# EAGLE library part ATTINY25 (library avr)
MICROCONTROLLER 2 Kbytes FLASH 128 bytes EEPROM 128 bytes RAM 4-channel 10 bit ADC USI
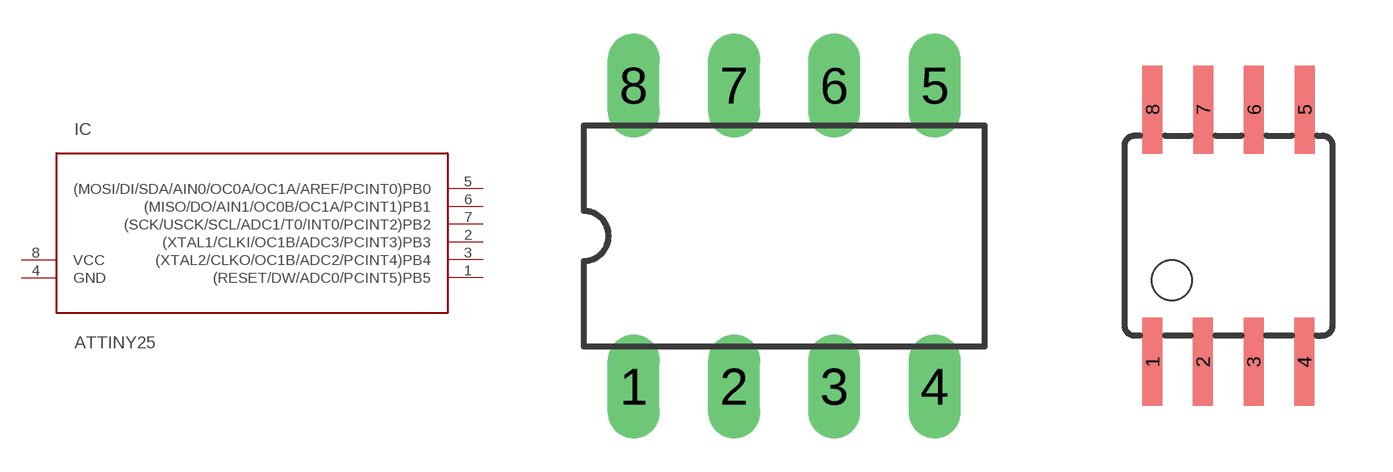
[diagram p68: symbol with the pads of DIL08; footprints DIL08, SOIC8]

Designator prefix IC

## ATTINY25-20P, ATTINY25V-10P  [DIL08]
1  (RESET/DW/ADC0/PCINT5)PB5
2  (XTAL1/CLKI/OC1B/ADC3/PCINT3)PB3
3  (XTAL2/CLKO/OC1B/ADC2/PCINT4)PB4
4  GND
5  (MOSI/DI/SDA/AIN0/OC0A/OC1A/AREF/PCINT0)PB0
6  (MISO/DO/AIN1/OC0B/OC1A/PCINT1)PB1
7  (SCK/USCK/SCL/ADC1/T0/INT0/PCINT2)PB2
8  VCC

## ATTINY25-20S, ATTINY25V-10S  [SOIC8]
Pads as for DIL08

## Footprint DIL08 (pad centres in mm)
Dual In Line
drill 0.813 long: 1 -3.81,-3.81; 2 -1.27,-3.81; 3 1.27,-3.81; 4 3.81,-3.81; 5 3.81,3.81; 6 1.27,3.81; 7 -1.27,3.81; 8 -3.81,3.81

## Footprint SOIC8 (pad centres in mm)
Wide Plastic Gull Wing Small Outline Package
smd 0.5 x 2.2: 1 -1.905,-3.154; 2 -0.645,-3.154; 3 0.625,-3.154; 4 1.895,-3.154; 5 1.905,3.154; 6 0.635,3.154; 7 -0.635,3.154; 8 -1.905,3.154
